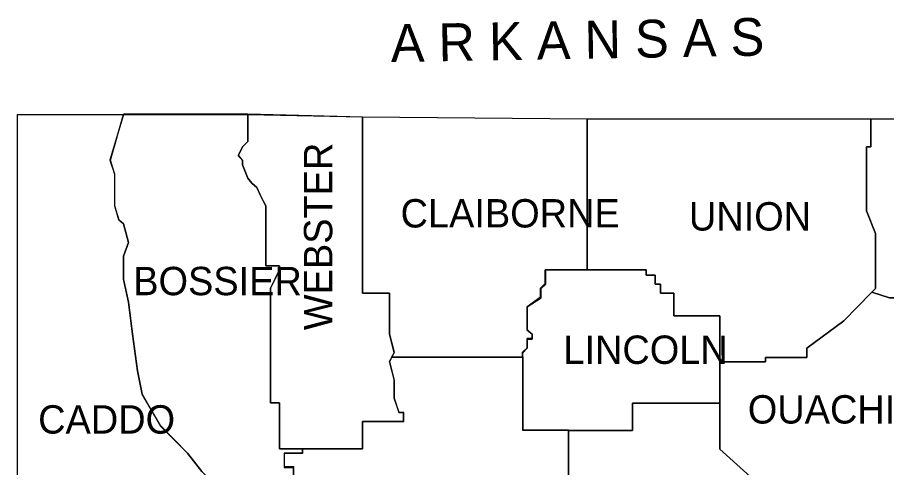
# Model space of a CAD drawing. Extents: x 0.23 to 2.82, y 0.04 to 1.79.
# Drawn here: x 2.2159 to 2.3593, y 1.6923 to 1.7666 of the extents above; entities that cross this region are included whole.
import ezdxf

# ---------------------------------------------------------------- set-up
doc = ezdxf.new("R2010")
doc.units = 0
for name, color, linetype in [('Dist04', 7, 'Continuous'), ('Dist05', 7, 'Continuous'), ('Standard Info', 7, 'Continuous')]:
    doc.layers.add(name, color=color, linetype=linetype)

msp = doc.modelspace()

# ---------------------------------------------------------------- linework, layer by layer
at = {"layer": 'Dist04'}
for p, q in [((2.2159, 1.678), (2.2159, 1.75058)), ((2.2159, 1.75058), (2.23332, 1.75058)), ((2.2334, 1.75067), (2.2539, 1.75067)), ((2.2539, 1.75067), (2.27282, 1.75017)), ((2.27282, 1.75017), (2.3099, 1.74983))]:
    msp.add_line(p, q, dxfattribs=at)
for points in [[(2.3099, 1.74983), (2.3099, 1.72492)], [(2.3099, 1.72492), (2.30299, 1.72492), (2.30299, 1.72267), (2.30224, 1.72192), (2.30224, 1.72042), (2.29999, 1.71883), (2.29999, 1.71508), (2.30082, 1.71433), (2.30082, 1.71358), (2.29999, 1.71358), (2.29999, 1.71208), (2.29924, 1.71133), (2.29924, 1.7105)], [(2.29932, 1.71058), (2.29932, 1.6985), (2.30682, 1.6985)], [(2.30682, 1.6985), (2.30682, 1.67958), (2.3054, 1.67883), (2.3054, 1.6765), (2.3054, 1.67575), (2.3039, 1.67575), (2.30307, 1.67508), (2.30307, 1.67275)]]:
    msp.add_lwpolyline(points, dxfattribs=at)
at = {"layer": 'Dist05'}
for p, q in [((2.3099, 1.74983), (2.35674, 1.74983)), ((2.35674, 1.74983), (2.40215, 1.74983))]:
    msp.add_line(p, q, dxfattribs=at)
for points in [[(2.3099, 1.72492), (2.3099, 1.74983)], [(2.29924, 1.7105), (2.29924, 1.71133), (2.29999, 1.71208), (2.29999, 1.71358), (2.30082, 1.71358), (2.30082, 1.71433), (2.29999, 1.71508), (2.29999, 1.71883), (2.30224, 1.72042), (2.30224, 1.72192), (2.30299, 1.72267), (2.30299, 1.72492), (2.3099, 1.72492)], [(2.30682, 1.6985), (2.29932, 1.6985), (2.29932, 1.71058)], [(2.30307, 1.67275), (2.30307, 1.67508), (2.3039, 1.67575), (2.3054, 1.67575), (2.3054, 1.6765), (2.3054, 1.67883), (2.30682, 1.67958), (2.30682, 1.6985)]]:
    msp.add_lwpolyline(points, dxfattribs=at)
at = {"layer": 'Standard Info'}
for p, q in [((2.2159, 1.67792), (2.2159, 1.75058)), ((2.2159, 1.75058), (2.23332, 1.75058)), ((2.23332, 1.75058), (2.2334, 1.75058)), ((2.2334, 1.75058), (2.2539, 1.75058)), ((2.2539, 1.75058), (2.27282, 1.75017)), ((2.27282, 1.75017), (2.3099, 1.74983)), ((2.3099, 1.74983), (2.35674, 1.74983)), ((2.35674, 1.74983), (2.40215, 1.74983)), ((2.3569, 1.72125), (2.35749, 1.72183)), ((2.27732, 1.70983), (2.27774, 1.71058)), ((2.2629, 1.69542), (2.25915, 1.69542))]:
    msp.add_line(p, q, dxfattribs=at)
for points in [[(2.2334, 1.75058), (2.23115, 1.743), (2.2319, 1.74075), (2.2319, 1.73775), (2.2319, 1.7355), (2.23265, 1.73317), (2.2334, 1.7325), (2.23424, 1.72942), (2.2334, 1.72717), (2.2334, 1.72333), (2.23424, 1.71958), (2.2349, 1.71433), (2.23574, 1.70825), (2.23649, 1.70442), (2.23949, 1.69917), (2.24399, 1.69467), (2.24632, 1.69167)], [(2.25615, 1.68108), (2.25457, 1.68258), (2.25307, 1.68483), (2.25082, 1.68708), (2.24857, 1.68933), (2.24632, 1.69167), (2.24399, 1.69467), (2.23949, 1.69925), (2.23649, 1.70442), (2.23574, 1.70825), (2.2349, 1.71433), (2.23424, 1.71958), (2.2334, 1.72342), (2.2334, 1.72717), (2.23424, 1.72942), (2.2334, 1.7325), (2.23265, 1.73317), (2.23199, 1.7355), (2.23199, 1.73775), (2.23199, 1.74067), (2.23124, 1.743), (2.2334, 1.75058)], [(2.2539, 1.75058), (2.2539, 1.74608), (2.25307, 1.74525), (2.25232, 1.74375), (2.25307, 1.743), (2.25307, 1.74225), (2.2539, 1.74008), (2.25457, 1.73925), (2.2554, 1.7385), (2.25615, 1.73692), (2.2569, 1.7355), (2.2569, 1.73317), (2.2569, 1.73017), (2.2569, 1.72858), (2.2569, 1.72792), (2.2569, 1.72642), (2.2569, 1.72558), (2.25915, 1.72558), (2.25915, 1.72492), (2.25765, 1.72192), (2.25765, 1.703), (2.25915, 1.703), (2.25915, 1.69542), (2.2629, 1.69542), (2.2629, 1.69467), (2.2599, 1.69467), (2.2599, 1.69233), (2.2614, 1.69233), (2.2614, 1.69083)], [(2.25915, 1.69542), (2.25915, 1.703), (2.25765, 1.703), (2.25765, 1.72183), (2.25915, 1.72492), (2.25915, 1.72558), (2.2569, 1.72558), (2.2569, 1.72642), (2.2569, 1.72792), (2.2569, 1.72867), (2.2569, 1.73017), (2.2569, 1.73317), (2.2569, 1.7355), (2.25615, 1.737), (2.2554, 1.7385), (2.25457, 1.73925), (2.2539, 1.74008), (2.25307, 1.74225), (2.25307, 1.743), (2.2524, 1.74383), (2.25307, 1.74525), (2.2539, 1.74608), (2.2539, 1.75058)], [(2.27282, 1.75017), (2.27282, 1.72108), (2.27732, 1.72108), (2.27732, 1.7165), (2.27732, 1.71433), (2.27807, 1.71133), (2.27732, 1.70975), (2.27807, 1.70675), (2.27807, 1.70375), (2.27882, 1.70142), (2.27957, 1.70142), (2.27957, 1.69992), (2.27282, 1.69992), (2.27282, 1.69542), (2.2629, 1.69542)], [(2.27765, 1.7105), (2.27807, 1.71125), (2.27732, 1.71433), (2.27732, 1.7165), (2.27732, 1.72108), (2.27282, 1.72108), (2.27282, 1.75017)], [(2.3099, 1.74983), (2.3099, 1.72492)], [(2.3099, 1.72492), (2.3099, 1.74983)], [(2.35674, 1.74983), (2.35674, 1.74525), (2.35599, 1.74525), (2.35599, 1.743), (2.35599, 1.73467), (2.35749, 1.73092), (2.35749, 1.72792), (2.35749, 1.72492), (2.35749, 1.72183), (2.35674, 1.72108), (2.35449, 1.71883), (2.35224, 1.7165), (2.34615, 1.712), (2.34615, 1.7105), (2.33932, 1.7105), (2.33932, 1.70975), (2.33182, 1.70975)], [(2.35749, 1.72183), (2.35749, 1.72492), (2.35749, 1.72792), (2.35749, 1.73092), (2.35599, 1.73467), (2.35599, 1.743), (2.35599, 1.74525), (2.35674, 1.74525), (2.35674, 1.74983)], [(2.3099, 1.72492), (2.30299, 1.72492), (2.30299, 1.72258), (2.30224, 1.72183), (2.30224, 1.72033), (2.29999, 1.71883), (2.29999, 1.715), (2.30082, 1.71433), (2.30082, 1.7135), (2.29999, 1.7135), (2.29999, 1.712), (2.29924, 1.71125), (2.29924, 1.7105)], [(2.29932, 1.7105), (2.29932, 1.71125), (2.29999, 1.712), (2.29999, 1.7135), (2.30082, 1.7135), (2.30082, 1.71433), (2.29999, 1.715), (2.29999, 1.71883), (2.30232, 1.72033), (2.30232, 1.72183), (2.30307, 1.72258), (2.30307, 1.72492), (2.3099, 1.72492)], [(2.29932, 1.7105), (2.29932, 1.71125), (2.29999, 1.712), (2.29999, 1.7135), (2.30082, 1.7135), (2.30082, 1.71433), (2.29999, 1.715), (2.29999, 1.71883), (2.30232, 1.72033), (2.30232, 1.72183), (2.30307, 1.72258), (2.30307, 1.72492), (2.3099, 1.72492)], [(2.33182, 1.70975), (2.33182, 1.71733), (2.32424, 1.71733), (2.32424, 1.72108), (2.32199, 1.72108), (2.32199, 1.72258), (2.32115, 1.72258), (2.32115, 1.72408), (2.31965, 1.72408), (2.31965, 1.72492), (2.3099, 1.72492)], [(2.3099, 1.72492), (2.31965, 1.72492), (2.31965, 1.72408), (2.32115, 1.72408), (2.32115, 1.72258), (2.32199, 1.72258), (2.32199, 1.72108), (2.32424, 1.72108), (2.32424, 1.71733), (2.33182, 1.71733), (2.33182, 1.70975), (2.33182, 1.70292)], [(2.33182, 1.70975), (2.33932, 1.70975), (2.33932, 1.7105), (2.34615, 1.7105), (2.34615, 1.712), (2.35224, 1.7165), (2.35449, 1.71883), (2.3569, 1.72125)], [(2.3569, 1.72125), (2.35982, 1.72033), (2.36282, 1.72033), (2.36432, 1.71883), (2.36582, 1.71733), (2.36807, 1.71733), (2.36882, 1.7165), (2.36807, 1.71583), (2.36732, 1.715), (2.36732, 1.712), (2.36582, 1.712), (2.36582, 1.709), (2.36732, 1.709), (2.36882, 1.70592), (2.36882, 1.70367), (2.36732, 1.70217), (2.36582, 1.70217), (2.36582, 1.69917), (2.36507, 1.69917), (2.36507, 1.69767), (2.36132, 1.69308), (2.36132, 1.68783), (2.36049, 1.68783), (2.36049, 1.68408)], [(2.36882, 1.70592), (2.36732, 1.709), (2.36582, 1.709), (2.36582, 1.712), (2.36732, 1.712), (2.36732, 1.715), (2.36807, 1.71583), (2.36882, 1.7165), (2.36807, 1.71733), (2.36582, 1.71733), (2.36432, 1.71883), (2.36282, 1.72033), (2.35982, 1.72033), (2.3569, 1.72125)], [(2.26299, 1.69542), (2.27282, 1.69542), (2.27282, 1.69992), (2.27965, 1.69992), (2.27965, 1.70142), (2.2789, 1.70142), (2.27807, 1.70375), (2.27807, 1.70683), (2.27732, 1.70983)], [(2.29924, 1.7105), (2.27765, 1.7105)], [(2.27774, 1.71058), (2.29932, 1.71058)], [(2.29932, 1.71058), (2.29932, 1.6985), (2.30682, 1.6985)], [(2.30682, 1.69842), (2.29932, 1.69842), (2.29932, 1.7105)], [(2.34015, 1.68408), (2.34015, 1.68783), (2.33182, 1.69533), (2.33182, 1.70292), (2.33182, 1.70975)], [(2.33182, 1.70292), (2.3174, 1.70292), (2.3174, 1.69842), (2.30682, 1.69842)], [(2.30682, 1.69842), (2.3174, 1.69842), (2.3174, 1.70292), (2.33182, 1.70292)], [(2.33182, 1.70292), (2.33182, 1.69533), (2.34015, 1.68783), (2.34015, 1.68408)], [(2.30682, 1.6985), (2.30682, 1.67958), (2.3054, 1.67875), (2.3054, 1.6765), (2.3054, 1.67575), (2.3039, 1.67575), (2.30307, 1.675), (2.30307, 1.67267)], [(2.30307, 1.67267), (2.30307, 1.675), (2.30382, 1.67567), (2.30532, 1.67567), (2.30532, 1.6765), (2.30532, 1.67875), (2.30682, 1.6795), (2.30682, 1.69842)], [(2.25999, 1.68025), (2.26065, 1.681), (2.26065, 1.68183), (2.26065, 1.68333), (2.26065, 1.68483), (2.25999, 1.68483), (2.25924, 1.68783), (2.26065, 1.68783), (2.26065, 1.69092), (2.26149, 1.69092), (2.26149, 1.69242), (2.25999, 1.69242), (2.25999, 1.69467), (2.26299, 1.69467), (2.26299, 1.69542)]]:
    msp.add_lwpolyline(points, dxfattribs=at)

# ---------------------------------------------------------------- texts
for s, height, rotation, p in [('A R K A N S A S', 0.0062368, 1.0059, (2.27755, 1.7592)), ('WEBSTER', 0.004679, 90, (2.26786, 1.71498))]:
    msp.add_text(s, height=height, rotation=rotation, dxfattribs=at).set_placement(p)
for s, p in [('CLAIBORNE', (2.27913, 1.73192)), ('UNION', (2.3267, 1.73142)), ('BOSSIER', (2.23502, 1.72075)), ('LINCOLN', (2.30599, 1.70942)), ('OUACHITA', (2.33642, 1.69958)), ('CADDO', (2.21933, 1.69792))]:
    msp.add_text(s, height=0.004679, dxfattribs=at).set_placement(p)

doc.saveas('drawing.dxf')
